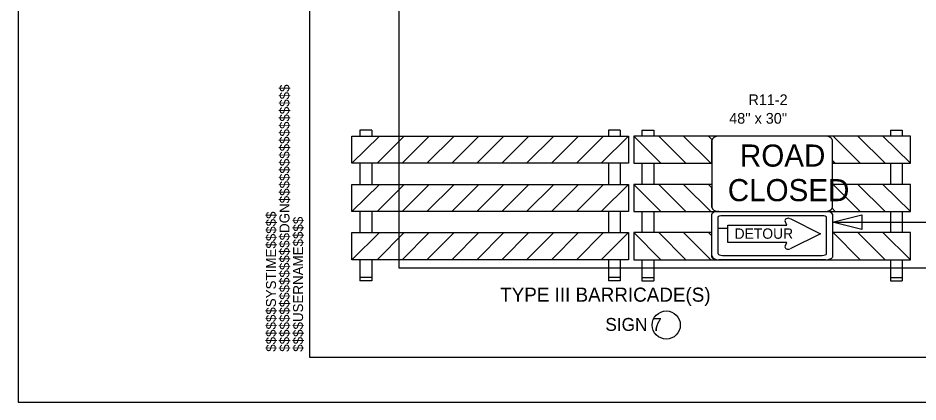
# Model space of a CAD drawing. Extents: x 1615234 to 1620694, y 898143 to 902846.
# Drawn here: x 1615234 to 1616745, y 899546 to 900191 of the extents above; entities that cross this region are included whole.
import ezdxf

# ---------------------------------------------------------------- set-up
doc = ezdxf.new("R2010")
doc.units = 0
for name, color, linetype in [('DEV BORDER CELL', 7, 'Continuous'), ('DEV TYPE 3 BARRICADE DOUBLE WITH R11-2 CELL', 7, 'Continuous'), ('DEV TYPE 3 BARRICADE WITH R11-2 M4-10R CELL', 7, 'Continuous'), ('Old_Level_28', 7, 'Continuous'), ('Scratch_Level_0', 7, 'Continuous'), ('Sheet Plot Border Outside CELL', 7, 'Continuous')]:
    doc.layers.add(name, color=color, linetype=linetype)

msp = doc.modelspace()

# ---------------------------------------------------------------- linework, layer by layer
at = {"layer": 'DEV BORDER CELL'}
msp.add_line((1615723.1, 899621.2), (1615723.1, 899621.2), dxfattribs=at)
msp.add_lwpolyline([(1620223.1, 902771.2), (1615723.1, 902771.2), (1615723.1, 899621.2), (1620223.1, 899621.2)], close=True, dxfattribs=at)
at = {"layer": 'DEV TYPE 3 BARRICADE DOUBLE WITH R11-2 CELL'}
for p, q in [((1615794.2, 899992.4), (1616258.5, 899992.4)), ((1615794.2, 899946.8), (1615794.2, 899992.4)), ((1615794.2, 899946.8), (1615794.2, 899992.4)), ((1615794.2, 899992.4), (1615840.6, 899992.4)), ((1615840.6, 899992.4), (1615794.2, 899946.8)), ((1615827.7, 900002.2), (1615808, 900002.2)), ((1615808, 900002.2), (1615808, 899992.4)), ((1615827.7, 900002.2), (1615827.7, 899992.4)), ((1615836.8, 899946.8), (1615882.3, 899992.4)), ((1615924.1, 899992.4), (1615878.6, 899946.8)), ((1615882.3, 899992.4), (1615924.1, 899992.4)), ((1615920.4, 899946.8), (1615965.9, 899992.4)), ((1616007.6, 899992.4), (1615962.1, 899946.8)), ((1615965.9, 899992.4), (1616007.6, 899992.4)), ((1616004.1, 899946.8), (1616049.6, 899992.4)), ((1616091.4, 899992.4), (1616045.9, 899946.8)), ((1616049.6, 899992.4), (1616091.4, 899992.4)), ((1616087.6, 899946.8), (1616133.2, 899992.4)), ((1616174.9, 899992.4), (1616129.4, 899946.8)), ((1616133.2, 899992.4), (1616174.9, 899992.4)), ((1616171.2, 899946.8), (1616216.7, 899992.4)), ((1616258.5, 899992.4), (1616213, 899946.8)), ((1616216.7, 899992.4), (1616258.5, 899992.4)), ((1616244.7, 900002.2), (1616225, 900002.2)), ((1616225, 900002.2), (1616225, 899992.4)), ((1616244.7, 900002.2), (1616244.7, 899992.4)), ((1616258.5, 899992.4), (1616258.5, 899946.8)), ((1616731.8, 899992.4), (1616267.5, 899992.4)), ((1616267.5, 899992.4), (1616267.5, 899946.8)), ((1616309.3, 899992.4), (1616267.5, 899992.4)), ((1616267.5, 899992.4), (1616313.1, 899946.8)), ((1616281.3, 900002.2), (1616301, 900002.2)), ((1616281.3, 900002.2), (1616281.3, 899992.4)), ((1616301, 900002.2), (1616301, 899992.4)), ((1616354.8, 899946.8), (1616309.3, 899992.4)), ((1616392.9, 899992.4), (1616351.1, 899992.4)), ((1616351.1, 899992.4), (1616396.6, 899946.8)), ((1616398.7, 899986.5), (1616392.9, 899992.4)), ((1616643.7, 899992.4), (1616601.9, 899992.4)), ((1616601.9, 899992.4), (1616647.4, 899946.8)), ((1616689.2, 899946.8), (1616643.7, 899992.4)), ((1616731.8, 899992.4), (1616685.5, 899992.4)), ((1616685.5, 899992.4), (1616731.8, 899946.8)), ((1616698.3, 900002.2), (1616718, 900002.2)), ((1616698.3, 900002.2), (1616698.3, 899992.4)), ((1616718, 900002.2), (1616718, 899992.4)), ((1616731.8, 899946.8), (1616731.8, 899992.4)), ((1616731.8, 899946.8), (1616731.8, 899992.4)), ((1616398.5, 899946.8), (1616398.5, 899985)), ((1616605.7, 899946.8), (1616600.9, 899951.7)), ((1616600.9, 899951.7), (1616600.9, 899946.8)), ((1616258.5, 899946.8), (1615794.2, 899946.8)), ((1615808, 899946.8), (1615808, 899911.4)), ((1615827.7, 899946.8), (1615827.7, 899911.4)), ((1615878.6, 899946.8), (1615836.8, 899946.8)), ((1615962.1, 899946.8), (1615920.4, 899946.8)), ((1616045.9, 899946.8), (1616004.1, 899946.8)), ((1616129.4, 899946.8), (1616087.6, 899946.8)), ((1616213, 899946.8), (1616171.2, 899946.8)), ((1616225, 899946.8), (1616225, 899911.4)), ((1616244.7, 899946.8), (1616244.7, 899911.4)), ((1616267.5, 899946.8), (1616398.5, 899946.8)), ((1616281.3, 899946.8), (1616281.3, 899911.4)), ((1616301, 899946.8), (1616301, 899911.4)), ((1616313.1, 899946.8), (1616354.8, 899946.8)), ((1616396.6, 899946.8), (1616398.5, 899946.8)), ((1616600.9, 899946.8), (1616605.7, 899946.8)), ((1616600.9, 899946.8), (1616731.8, 899946.8)), ((1616647.4, 899946.8), (1616689.2, 899946.8)), ((1616698.3, 899946.8), (1616698.3, 899911.4)), ((1616718, 899946.8), (1616718, 899911.4)), ((1615794.2, 899911.4), (1616258.5, 899911.4)), ((1615794.2, 899865.9), (1615794.2, 899911.4)), ((1615794.2, 899865.9), (1615794.2, 899911.4)), ((1615794.2, 899911.4), (1615840.6, 899911.4)), ((1615840.6, 899911.4), (1615794.2, 899865.9)), ((1615836.8, 899865.9), (1615882.3, 899911.4)), ((1615924.1, 899911.4), (1615878.6, 899865.9)), ((1615882.3, 899911.4), (1615924.1, 899911.4)), ((1615920.4, 899865.9), (1615965.9, 899911.4)), ((1616007.6, 899911.4), (1615962.1, 899865.9)), ((1615965.9, 899911.4), (1616007.6, 899911.4)), ((1616004.1, 899865.9), (1616049.6, 899911.4)), ((1616091.4, 899911.4), (1616045.9, 899865.9)), ((1616049.6, 899911.4), (1616091.4, 899911.4)), ((1616087.6, 899865.9), (1616133.2, 899911.4)), ((1616174.9, 899911.4), (1616129.4, 899865.9)), ((1616133.2, 899911.4), (1616174.9, 899911.4)), ((1616171.2, 899865.9), (1616216.7, 899911.4)), ((1616258.5, 899911.4), (1616213, 899865.9)), ((1616216.7, 899911.4), (1616258.5, 899911.4)), ((1616258.5, 899911.4), (1616258.5, 899865.9)), ((1616267.5, 899911.4), (1616267.5, 899865.9)), ((1616309.3, 899911.4), (1616267.5, 899911.4)), ((1616267.5, 899911.4), (1616313.1, 899865.9)), ((1616398.5, 899911.4), (1616267.5, 899911.4)), ((1616354.8, 899865.9), (1616309.3, 899911.4)), ((1616351.1, 899911.4), (1616396.6, 899865.9)), ((1616392.9, 899911.4), (1616351.1, 899911.4)), ((1616398.5, 899905.8), (1616392.9, 899911.4)), ((1616398.5, 899873.2), (1616398.5, 899905.8)), ((1616731.8, 899911.4), (1616600.9, 899911.4)), ((1616643.7, 899911.4), (1616601.9, 899911.4)), ((1616601.9, 899911.4), (1616647.4, 899865.9)), ((1616689.2, 899865.9), (1616643.7, 899911.4)), ((1616731.8, 899911.4), (1616685.5, 899911.4)), ((1616685.5, 899911.4), (1616731.8, 899865.9)), ((1616731.8, 899865.9), (1616731.8, 899911.4)), ((1616731.8, 899865.9), (1616731.8, 899911.4)), ((1616258.5, 899865.9), (1615794.2, 899865.9)), ((1615808, 899865.9), (1615808, 899830.4)), ((1615827.7, 899865.9), (1615827.7, 899830.4)), ((1615878.6, 899865.9), (1615836.8, 899865.9)), ((1615962.1, 899865.9), (1615920.4, 899865.9)), ((1616045.9, 899865.9), (1616004.1, 899865.9)), ((1616129.4, 899865.9), (1616087.6, 899865.9)), ((1616213, 899865.9), (1616171.2, 899865.9)), ((1616225, 899865.9), (1616225, 899830.4)), ((1616244.7, 899865.9), (1616244.7, 899830.4)), ((1616267.5, 899865.9), (1616731.8, 899865.9)), ((1616281.3, 899865.9), (1616281.3, 899830.4)), ((1616301, 899865.9), (1616301, 899830.4)), ((1616313.1, 899865.9), (1616354.8, 899865.9)), ((1616396.6, 899865.9), (1616410.2, 899865.9)), ((1616410.3, 899865.9), (1616589, 899865.9)), ((1616589, 899865.9), (1616605.7, 899865.9)), ((1616605.7, 899865.9), (1616600.4, 899871.2)), ((1616647.4, 899865.9), (1616689.2, 899865.9)), ((1616698.3, 899865.9), (1616698.3, 899830.4)), ((1616718, 899865.9), (1616718, 899830.4)), ((1615794.2, 899784.9), (1615794.2, 899830.4)), ((1615794.2, 899830.4), (1615840.6, 899830.4)), ((1615840.6, 899830.4), (1615794.2, 899784.9)), ((1615794.2, 899830.4), (1616258.5, 899830.4)), ((1615794.2, 899784.9), (1615794.2, 899830.4)), ((1615836.8, 899784.9), (1615882.3, 899830.4)), ((1615924.1, 899830.4), (1615878.6, 899784.9)), ((1615882.3, 899830.4), (1615924.1, 899830.4)), ((1615920.4, 899784.9), (1615965.9, 899830.4)), ((1616007.6, 899830.4), (1615962.1, 899784.9)), ((1615965.9, 899830.4), (1616007.6, 899830.4)), ((1616004.1, 899784.9), (1616049.6, 899830.4)), ((1616091.4, 899830.4), (1616045.9, 899784.9)), ((1616049.6, 899830.4), (1616091.4, 899830.4)), ((1616087.6, 899784.9), (1616133.2, 899830.4)), ((1616174.9, 899830.4), (1616129.4, 899784.9)), ((1616133.2, 899830.4), (1616174.9, 899830.4)), ((1616171.2, 899784.9), (1616216.7, 899830.4)), ((1616258.5, 899830.4), (1616213, 899784.9)), ((1616216.7, 899830.4), (1616258.5, 899830.4)), ((1616258.5, 899830.4), (1616258.5, 899784.9)), ((1616309.3, 899830.4), (1616267.5, 899830.4)), ((1616267.5, 899830.4), (1616313.1, 899784.9)), ((1616267.5, 899830.4), (1616267.5, 899784.9)), ((1616398.5, 899830.4), (1616267.5, 899830.4)), ((1616354.8, 899784.9), (1616309.3, 899830.4)), ((1616731.8, 899830.4), (1616600.8, 899830.4)), ((1616643.7, 899830.4), (1616601.9, 899830.4)), ((1616601.9, 899830.4), (1616647.4, 899784.9)), ((1616689.2, 899784.9), (1616643.7, 899830.4)), ((1616731.8, 899830.4), (1616685.5, 899830.4)), ((1616685.5, 899830.4), (1616731.8, 899784.9)), ((1616731.8, 899784.9), (1616731.8, 899830.4)), ((1616731.8, 899784.9), (1616731.8, 899830.4)), ((1616258.5, 899784.9), (1615794.2, 899784.9)), ((1615808, 899784.9), (1615808, 899749.4)), ((1615827.7, 899784.9), (1615827.7, 899749.4)), ((1615878.6, 899784.9), (1615836.8, 899784.9)), ((1615962.1, 899784.9), (1615920.4, 899784.9)), ((1616045.9, 899784.9), (1616004.1, 899784.9)), ((1616129.4, 899784.9), (1616087.6, 899784.9)), ((1616213, 899784.9), (1616171.2, 899784.9)), ((1616225, 899784.9), (1616225, 899749.4)), ((1616244.7, 899784.9), (1616244.7, 899749.4)), ((1616267.5, 899784.9), (1616731.8, 899784.9)), ((1616281.3, 899784.9), (1616281.3, 899749.4)), ((1616301, 899784.9), (1616301, 899749.4)), ((1616313.1, 899784.9), (1616354.8, 899784.9)), ((1616647.4, 899784.9), (1616689.2, 899784.9)), ((1616698.3, 899784.9), (1616698.3, 899749.4)), ((1616718, 899784.9), (1616718, 899749.4)), ((1615827.7, 899755.3), (1615808, 899755.3)), ((1616244.7, 899755.3), (1616225, 899755.3)), ((1616281.3, 899755.3), (1616301, 899755.3)), ((1616698.3, 899755.3), (1616718, 899755.3)), ((1615827.7, 899749.4), (1615808, 899749.4)), ((1616244.7, 899749.4), (1616225, 899749.4)), ((1616281.3, 899749.4), (1616301, 899749.4)), ((1616698.3, 899749.4), (1616718, 899749.4))]:
    msp.add_line(p, q, dxfattribs=at)
for points in [[(1616589, 899992.4), (1616410.3, 899992.4)], [(1616398.5, 899985), (1616398.5, 899873.2)], [(1616600.9, 899873.2), (1616600.9, 899985)]]:
    msp.add_lwpolyline(points, dxfattribs=at)
for centre, major_axis, start_param, end_param in [((1616410.3, 899985), (-11.8, 0), 4.712389, 6.283185), ((1616589, 899985), (11.8, 0), 0, 1.571024), ((1616410.3, 899985), (-11.8, 0), 6.074789, 6.283185), ((1616410.3, 899873.2), (11.8, 0), 3.141593, 4.712389), ((1616410.3, 899873.2), (-11.8, 0), 0, 1.570796), ((1616589, 899873.2), (11.8, 0), 4.712162, 6.283185), ((1616589, 899873.2), (11.8, 0), 4.712497, 5.996053)]:
    msp.add_ellipse(centre, major_axis=major_axis, ratio=0.625, start_param=start_param, end_param=end_param, dxfattribs=at)
at = {"layer": 'DEV TYPE 3 BARRICADE WITH R11-2 M4-10R CELL'}
for p, q in [((1616583.5, 899858.6), (1616416.3, 899858.8)), ((1616408.6, 899856.1), (1616408.6, 899838.1)), ((1616425.4, 899838.1), (1616425.4, 899842.9)), ((1616425.4, 899842.9), (1616524.4, 899842.9)), ((1616524.4, 899842.9), (1616521.4, 899849.5)), ((1616529.7, 899854), (1616580.9, 899828.3)), ((1616591, 899794.7), (1616591, 899856.1)), ((1616600.8, 899848.2), (1616958.3, 899848.2)), ((1616351.1, 899830.4), (1616396.6, 899784.9)), ((1616392.9, 899830.4), (1616351.1, 899830.4)), ((1616398.5, 899824.8), (1616392.9, 899830.4)), ((1616408.6, 899838.1), (1616425.4, 899838.1)), ((1616425.4, 899837.6), (1616408.6, 899837.6)), ((1616408.6, 899837.6), (1616408.8, 899794.7)), ((1616425.4, 899814.1), (1616425.4, 899837.6)), ((1616580.9, 899828.3), (1616529.7, 899803.3)), ((1616398.5, 899792.3), (1616398.5, 899824.8)), ((1616524.4, 899814.1), (1616425.4, 899814.1)), ((1616521.4, 899807.7), (1616524.4, 899814.1)), ((1616396.6, 899784.9), (1616410.2, 899784.9)), ((1616589, 899784.9), (1616410.3, 899784.9)), ((1616416.5, 899792.2), (1616583.5, 899792.2))]:
    msp.add_line(p, q, dxfattribs=at)
for points in [[(1616398.5, 899789.3), (1616398.5, 899861.4)], [(1616410.3, 899865.9), (1616589, 899865.9)], [(1616600.8, 899861.4), (1616600.8, 899789.3)]]:
    msp.add_lwpolyline(points, dxfattribs=at)
msp.add_lwpolyline([(1616650.1, 899835.8), (1616600.8, 899848.2), (1616650.1, 899860.5)], close=True, dxfattribs=at)
msp.add_lwpolyline([(1616650.1, 899835.8), (1616600.8, 899848.2), (1616650.1, 899860.5)], close=True, dxfattribs=at)
for centre, major_axis, ratio, start_param, end_param in [((1616410.3, 899861.4), (-11.8, 0), 0.375009, 4.712162, 6.283185), ((1616416.4, 899856.1), (-7.59, 0), 0.337508, 4.712581, 6.283188), ((1616583.4, 899856.1), (7.59, 0), 0.337508, 6.283178, 7.854173), ((1616589, 899861.4), (11.8, 0), 0.375009, 0, 1.570796), ((1616526.6, 899850.6), (5.42, 0), 0.720018, 0.96961, 3.452569), ((1616526.6, 899806.5), (5.42, 0), 0.720018, 2.830617, 5.313577), ((1616410.3, 899792.3), (11.8, 0), 0.625, 3.141593, 4.712389), ((1616410.3, 899789.3), (-11.8, 0), 0.375009, 0, 1.570796), ((1616416.5, 899794.7), (-7.59, 0), 0.337508, 0.000003, 1.57061), ((1616583.5, 899794.7), (7.59, 0), 0.337508, 4.712203, 6.283178), ((1616589, 899789.3), (-11.8, 0), 0.375009, 1.570796, 3.141593)]:
    msp.add_ellipse(centre, major_axis=major_axis, ratio=ratio, start_param=start_param, end_param=end_param, dxfattribs=at)
at = {"layer": 'Old_Level_28'}
msp.add_circle((1616322, 899675.4), 23.6, dxfattribs=at)
at = {"layer": 'Scratch_Level_0'}
msp.add_lwpolyline([(1620073.1, 902621.2), (1615873.1, 902621.2), (1615873.1, 899771.2), (1618509.6, 899771.2), (1618509.6, 900126), (1620073.1, 900126)], close=True, dxfattribs=at)
at = {"layer": 'Sheet Plot Border Outside CELL'}
msp.add_lwpolyline([(1615234.1, 899546.2), (1620298.1, 899546.2), (1620298.1, 902846.2), (1615234.1, 902846.2)], close=True, dxfattribs=at)

# ---------------------------------------------------------------- texts
at = {"layer": 'DEV BORDER CELL'}
for s, p in [('$$$$$$$$$$$$$$$$DGN$$$$$$$$$$$$$$$$', (1615689.7, 899630.5)), ('$$$$$$SYSTIME$$$$$', (1615667, 899630.5)), ('$$$$USERNAME$$$$', (1615712.5, 899630.5))]:
    msp.add_text(s, height=16.752, rotation=90, dxfattribs=at).set_placement(p)
at = {"layer": 'DEV TYPE 3 BARRICADE DOUBLE WITH R11-2 CELL'}
for s, height, p in [('R11-2', 18, (1616460.1, 900044.4)), ("48'' x 30''", 18, (1616427.7, 900013.2)), ('ROAD', 37.11, (1616445.7, 899941.2)), ('CLOSED', 37.11, (1616425.3, 899883.2)), ('TYPE III BARRICADE(S)', 23.645, (1616043.3, 899714.5))]:
    msp.add_text(s, height=height, rotation=360, dxfattribs=at).set_placement(p)
at = {"layer": 'DEV TYPE 3 BARRICADE WITH R11-2 M4-10R CELL'}
msp.add_text('DETOUR', height=17.4, rotation=360, dxfattribs=at).set_placement((1616436.7, 899820.1))
at = {"layer": 'Old_Level_28'}
msp.add_text('SIGN 7', height=21.6, dxfattribs=at).set_placement((1616219.8, 899665.6))

doc.saveas('drawing.dxf')
